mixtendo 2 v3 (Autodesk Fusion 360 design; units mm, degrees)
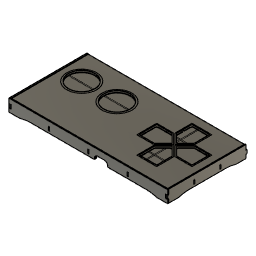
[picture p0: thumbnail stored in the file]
parameter "mt" = 12.7
sketch "Sketch1" plane through (0, 0, 0) normal (0, 0, 1) x axis (1, 0, 0)
  line L1 (12.7, 0) -> (0, 0)
  line L2 (12.7, 914.4) -> (12.7, 0)
  line L3 (0, 914.4) -> (12.7, 914.4)
  line L4 (0, 0) -> (0, 914.4)
  line L5 (1828.8, 0) -> (0, 0)
  line L6 (1828.8, 12.7) -> (1828.8, 0)
  line L7 (0, 12.7) -> (1828.8, 12.7)
  line L8 (0, 0) -> (0, 12.7)
  point P1 (0, 0)
  point P2 (0, 0)
  point P6 (0, 0)
  point P3 (12.7, 0)
  point P5 (0, 914.4)
  point P7 (1828.8, 0)
  point P9 (0, 12.7)
  horizontal L1
  vertical L2
  horizontal L3
  vertical L4
  coincident P1 P2
  horizontal L5
  vertical L6
  horizontal L7
  vertical L8
  coincident P1 P6
  dimension "d2" distance P2 P3 = 12.7 (= "mt")
  dimension "d3" distance P2 P5 = 914.4
  dimension "d4" distance P6 P7 = 1828.8
  dimension "d5" distance P6 P9 = 12.7 (= "mt")
extrude "Extrude1" new body sketch "Sketch1" profile of L1 L2 L3 L4 L5 L7 L8 along normal blind 127 bodies "left vert1"
extrude "Extrude2" new body sketch "Sketch1" profile of L1 L2 L4 L5 L6 L7 L8 along normal blind 139.7 bodies "front horizontal"
rectangular_pattern "R-Pattern1" uSpaceDistance 1816.1 (= "72 in - mt") vSpaceDistance 0 bodies "vert2", "vert3", "vert4", "right vert5"
rectangular_pattern "R-Pattern2" uSpaceDistance 901.7 (= "36 in - mt") vSpaceDistance 0 bodies "horizontal (1)", "horizontal (2)", "rear horiz"
sketch "Sketch2" plane through (0, 0, 127) normal (0, 0, 1) x axis (-1, 0, 0)
  line L1 (0, 0) -> (0, -914.4)
  line L2 (-12.7, 0) -> (0, 0)
  line L3 (-12.7, -914.4) -> (-12.7, 0)
  line L4 (0, -914.4) -> (-12.7, -914.4)
  line L5 (0, 0) -> (0, -12.7)
  line L6 (-1828.8, 0) -> (0, 0)
  line L7 (-1828.8, -12.7) -> (-1828.8, 0)
  line L8 (0, -12.7) -> (-1828.8, -12.7)
  line L9 (0, -20) -> (0, -2.5)
  line L10 (0, -901.7) -> (0, -914.4)
  line L11 (-1828.8, -901.7) -> (0, -901.7)
  line L12 (-1828.8, -914.4) -> (-1828.8, -901.7)
  line L13 (0, -914.4) -> (-1828.8, -914.4)
  line L14 (-1816.1, 0) -> (-1816.1, -914.4)
  line L15 (-1828.8, 0) -> (-1816.1, 0)
  line L16 (-1828.8, -914.4) -> (-1828.8, 0)
  line L17 (-1816.1, -914.4) -> (-1828.8, -914.4)
  line L18 (-1816.1, -901.7) -> (-1803.4, -901.7)
  line L19 (-1816.1, -12.7) -> (-1816.1, -901.7)
  line L20 (-25.4, -914.4) -> (-12.7, -914.4)
  line L21 (-25.4, 0) -> (-25.4, -914.4)
  line L22 (-12.7, 0) -> (-25.4, 0)
  line L23 (-12.7, -914.4) -> (-12.7, 0)
  line L24 (-1803.4, 0) -> (-1816.1, 0)
  line L25 (-1803.4, -914.4) -> (-1803.4, 0)
  line L26 (-1816.1, -914.4) -> (-1803.4, -914.4)
  line L27 (-1816.1, 0) -> (-1816.1, -914.4)
  line L28 (0, -901.7) -> (-1828.8, -901.7)
  line L29 (0, -889) -> (0, -901.7)
  line L30 (-1828.8, -889) -> (0, -889)
  line L31 (-1828.8, -901.7) -> (-1828.8, -889)
  line L32 (-1828.8, -12.7) -> (0, -12.7)
  line L33 (-1828.8, -25.4) -> (-1828.8, -12.7)
  line L34 (0, -25.4) -> (-1828.8, -25.4)
  line L35 (0, -12.7) -> (0, -25.4)
  point P21 (-1803.4, -901.7)
  point P20 (-1816.1, -12.7)
  point P25 (-25.4, 0)
  point P5 (-12.7, -914.4)
  point P23 (-12.7, -914.4)
  point P29 (-1803.4, -914.4)
  point P17 (-1816.1, 0)
  point P27 (-1816.1, 0)
  point P33 (0, -889)
  point P14 (-1828.8, -901.7)
  point P31 (-1828.8, -901.7)
  point P37 (-1828.8, -25.4)
  point P6 (0, -12.7)
  point P35 (0, -12.7)
  horizontal L18
  vertical L19
  coincident L11 P21
  coincident L8 P20
  coincident L14 P20
  horizontal L20
  vertical L21
  horizontal L22
  vertical L23
  coincident L6 P25
  coincident P5 P23
  horizontal L24
  vertical L25
  horizontal L26
  vertical L27
  coincident L13 P29
  coincident P17 P27
  horizontal L28
  vertical L29
  horizontal L30
  vertical L31
  coincident L1 P33
  coincident P14 P31
  horizontal L32
  vertical L33
  horizontal L34
  vertical L35
  coincident L16 P37
  coincident P6 P35
  dimension "d30" distance L21 L23 = 12.7 (= "mt")
  dimension "d31" distance L25 L27 = 12.7 (= "mt")
  dimension "d32" distance L28 L30 = 12.7 (= "mt")
  dimension "d33" distance L32 L34 = 12.7 (= "mt")
extrude "Extrude3" new body sketch "Sketch2" profile of L3 L8 L11 L14 L18 L19 L21 L23 L25 L27 L28 L30 L32 L34 against normal blind 127 bodies "front horiz sup", "rear horiz sup"
extrude "Extrude4" new body sketch "Sketch2" profile of L3 L6 L8 L11 L13 L14 L18 L19 L20 L21 L22 L23 L24 L25 L26 L27 L28 L30 L32 L34 against normal blind 127 bodies "left vert sup", "right vert sup"
sketch "Sketch4" plane through (0, 0, 0) normal (1, 0, 0) x axis (0, 1, 0)
  line L1 (0, 0) -> (914.4, 0)
  line L2 (0, 127) -> (0, 0)
  line L3 (914.4, 127) -> (0, 127)
  line L4 (914.4, 0) -> (914.4, 127)
  line L5 (457.2, 127) -> (457.2, 0)
  line L6 (25.4, 127) -> (0, 127)
  line L7 (25.4, 84.6667) -> (25.4, 127)
  line L8 (0, 84.6667) -> (25.4, 84.6667)
  line L9 (0, 127) -> (0, 84.6667)
  line L10 (0, 63.5) -> (457.2, 63.5)
  line L11 (25.4, 0) -> (0, 0)
  line L12 (25.4, 42.3333) -> (25.4, 0)
  line L13 (0, 0) -> (0, 42.3333)
  line L14 (0, 42.3333) -> (25.4, 42.3333)
  line L15 (889, 127) -> (914.4, 127)
  line L16 (889, 84.6667) -> (889, 127)
  line L17 (914.4, 127) -> (914.4, 84.6667)
  line L18 (914.4, 84.6667) -> (889, 84.6667)
  line L19 (889, 0) -> (914.4, 0)
  line L20 (889, 42.3333) -> (889, 0)
  line L21 (914.4, 0) -> (914.4, 42.3333)
  line L22 (914.4, 42.3333) -> (889, 42.3333)
  point P6 (457.2, 0)
  point P7 (457.2, 127)
  point P4 (0, 127)
  point P8 (0, 127)
  point P12 (457.2, 63.5)
  point P13 (0, 63.5)
  point P14 (0, 0)
  point P9 (25.4, 127)
  point P15 (25.4, 0)
  point P10 (25.4, 84.6667)
  point P16 (25.4, 42.3333)
  point P11 (0, 84.6667)
  point P17 (0, 42.3333)
  point P18 (914.4, 127)
  point P19 (889, 127)
  point P20 (889, 84.6667)
  point P21 (914.4, 84.6667)
  point P22 (914.4, 0)
  point P23 (889, 0)
  point P24 (889, 42.3333)
  point P25 (914.4, 42.3333)
  midpoint L1 P6
  midpoint L3 P7
  horizontal L6
  vertical L7
  horizontal L8
  vertical L9
  coincident P4 P8
  midpoint L5 P12
  midpoint L2 P13
  symmetric P8 L10 P14
  symmetric P9 L10 P15
  symmetric P10 L10 P16
  symmetric P11 L10 P17
  symmetric L5 P8 P18
  symmetric L5 P9 P19
  symmetric L5 P10 P20
  symmetric L5 P11 P21
  symmetric L5 P14 P22
  symmetric L5 P15 P23
  symmetric L5 P16 P24
  symmetric L5 P17 P25
  dimension "d26" distance P8 P9 = 25.4 (= "mt * 2")
  dimension "d27" distance P8 P11 = 42.3333 (= "( 5 / 3 ) * 1 in")
extrude "Extrude6" cut sketch "Sketch4" profile of L1 L2 L3 L4 L6 L7 L8 L9 L11 L12 L13 L14 L15 L16 L17 L18 L19 L20 L21 L22 to an object
combine "Combine1"
combine "Combine2"
combine "Combine3"
combine "Combine4"
sketch "Sketch5" plane through (0, 300.5667, 0) normal (0, -1, 0) x axis (1, 0, 0)
  line L1 (1828.8, 0) -> (0, 0)
  line L2 (1828.8, 139.7) -> (1828.8, 0)
  line L3 (0, 139.7) -> (1828.8, 139.7)
  line L4 (0, 0) -> (0, 139.7)
  line L5 (1374.775, 84.6667) -> (1362.075, 84.6667)
  line L6 (1374.775, 42.3333) -> (1374.775, 84.6667)
  line L7 (1362.075, 42.3333) -> (1374.775, 42.3333)
  line L8 (1362.075, 84.6667) -> (1362.075, 42.3333)
  line L9 (1803.4, 42.3333) -> (1828.8, 42.3333)
  line L10 (1803.4, 84.6667) -> (1803.4, 42.3333)
  line L11 (1828.8, 84.6667) -> (1803.4, 84.6667)
  line L12 (1828.8, 139.7) -> (1828.8, 84.6667)
  line L13 (0, 139.7) -> (1828.8, 139.7)
  line L14 (0, 84.6667) -> (0, 139.7)
  line L15 (25.4, 84.6667) -> (0, 84.6667)
  line L16 (25.4, 42.3333) -> (25.4, 84.6667)
  line L17 (0, 42.3333) -> (25.4, 42.3333)
  line L18 (0, 0) -> (0, 42.3333)
  line L19 (1828.8, 0) -> (0, 0)
  line L20 (1828.8, 42.3333) -> (1828.8, 0)
  line L21 (466.725, 84.6667) -> (454.025, 84.6667)
  line L22 (466.725, 42.3333) -> (466.725, 84.6667)
  line L23 (454.025, 42.3333) -> (466.725, 42.3333)
  line L24 (454.025, 84.6667) -> (454.025, 42.3333)
  line L25 (920.75, 84.6667) -> (908.05, 84.6667)
  line L26 (920.75, 42.3333) -> (920.75, 84.6667)
  line L27 (908.05, 42.3333) -> (920.75, 42.3333)
  line L28 (908.05, 84.6667) -> (908.05, 42.3333)
  line L29 (25.4, 84.6667) -> (0, 84.6667)
  line L30 (25.4, 139.7) -> (25.4, 84.6667)
  line L31 (0, 139.7) -> (25.4, 139.7)
  line L32 (0, 84.6667) -> (0, 139.7)
  line L33 (0, 42.3333) -> (25.4, 42.3333)
  line L34 (0, 0) -> (0, 42.3333)
  line L35 (25.4, 0) -> (0, 0)
  line L36 (25.4, 42.3333) -> (25.4, 0)
  line L37 (1828.8, 84.6667) -> (1803.4, 84.6667)
  line L38 (1828.8, 139.7) -> (1828.8, 84.6667)
  line L39 (1803.4, 139.7) -> (1828.8, 139.7)
  line L40 (1803.4, 84.6667) -> (1803.4, 139.7)
  line L41 (1828.8, 42.3333) -> (1803.4, 42.3333)
  line L42 (1828.8, 0) -> (1828.8, 42.3333)
  line L43 (1803.4, 0) -> (1828.8, 0)
  line L44 (1803.4, 42.3333) -> (1803.4, 0)
  point P32 (25.4, 139.7)
  point P16 (0, 84.6667)
  point P30 (0, 84.6667)
  point P2 (0, 0)
  point P36 (0, 0)
  point P18 (25.4, 42.3333)
  point P34 (25.4, 42.3333)
  point P14 (1828.8, 139.7)
  point P40 (1828.8, 139.7)
  point P12 (1803.4, 84.6667)
  point P38 (1803.4, 84.6667)
  point P21 (1828.8, 0)
  point P44 (1828.8, 0)
  point P11 (1803.4, 42.3333)
  point P42 (1803.4, 42.3333)
  horizontal L29
  vertical L30
  horizontal L31
  vertical L32
  coincident L3 P32
  coincident P16 P30
  horizontal L33
  vertical L34
  horizontal L35
  vertical L36
  coincident P2 P36
  coincident P18 P34
  horizontal L37
  vertical L38
  horizontal L39
  vertical L40
  coincident P14 P40
  coincident P12 P38
  horizontal L41
  vertical L42
  horizontal L43
  vertical L44
  coincident P21 P44
  coincident P11 P42
extrude "Extrude7" cut sketch "Sketch5" profile of L1 L2 L3 L4 L9 L11 L12 L13 L14 L15 L17 L18 L19 L20 L29 L30 L31 L32 L33 L34 L35 L36 L37 L38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 to an object
combine "Combine5"
combine "Combine6"
combine "Combine7"
combine "Combine8"
sketch "Sketch6" plane through (1828.8, 0, 0) normal (1, 0, 0) x axis (0, 1, 0)
  line L1 (313.2667, 84.6667) -> (300.5667, 84.6667)
  line L2 (313.2667, 42.3333) -> (313.2667, 84.6667)
  line L3 (300.5667, 42.3333) -> (313.2667, 42.3333)
  line L4 (300.5667, 84.6667) -> (300.5667, 42.3333)
  line L5 (613.8333, 84.6667) -> (601.1333, 84.6667)
  line L6 (613.8333, 42.3333) -> (613.8333, 84.6667)
  line L7 (601.1333, 42.3333) -> (613.8333, 42.3333)
  line L8 (601.1333, 84.6667) -> (601.1333, 42.3333)
  line L9 (25.4, 0) -> (25.4, 42.3333)
  line L10 (889, 0) -> (25.4, 0)
  line L11 (889, 42.3333) -> (889, 0)
  line L12 (914.4, 42.3333) -> (889, 42.3333)
  line L13 (914.4, 84.6667) -> (914.4, 42.3333)
  line L14 (889, 84.6667) -> (914.4, 84.6667)
  line L15 (889, 127) -> (889, 84.6667)
  line L16 (25.4, 127) -> (889, 127)
  line L17 (25.4, 84.6667) -> (25.4, 127)
  line L18 (0, 84.6667) -> (25.4, 84.6667)
  line L19 (0, 42.3333) -> (0, 84.6667)
  line L20 (25.4, 42.3333) -> (0, 42.3333)
  line L21 (313.2667, 127) -> (300.5667, 127)
  line L22 (313.2667, 63.5) -> (313.2667, 127)
  line L23 (300.5667, 63.5) -> (313.2667, 63.5)
  line L24 (300.5667, 127) -> (300.5667, 63.5)
  line L25 (601.1333, 127) -> (613.8333, 127)
  line L26 (601.1333, 63.5) -> (601.1333, 127)
  line L27 (613.8333, 63.5) -> (601.1333, 63.5)
  line L28 (613.8333, 127) -> (613.8333, 63.5)
  point P24 (313.2667, 63.5)
  point P22 (300.5667, 127)
  point P26 (613.8333, 127)
  horizontal L21
  vertical L22
  horizontal L23
  vertical L24
  coincident L2 P24
  coincident L16 P22
  horizontal L25
  vertical L26
  horizontal L27
  vertical L28
  coincident L16 P26
  dimension "d40" distance L21 L23 = 63.5
  dimension "d41" distance L22 L24 = 12.7 (= "mt")
  dimension "d42" distance L26 L28 = 12.7 (= "mt")
  dimension "d43" distance L25 L27 = 63.5
extrude "Extrude8" cut sketch "Sketch6" profile of L1 L2 L4 L5 L6 L8 L16 L21 L22 L23 L24 L25 L26 L27 L28 to an object
combine "Combine9"
combine "Combine10"
sketch "Sketch9" plane through (0, 0, 127) normal (0, 0, 1) x axis (-1, 0, 0)
  line L1 (0, -889) -> (-12.7, -889)
  line L2 (0, -25.4) -> (0, -889)
  line L3 (-12.7, -25.4) -> (0, -25.4)
  line L4 (-12.7, -889) -> (-12.7, -25.4)
  line L5 (0, 0) -> (0, -12.7)
  line L6 (-1828.8, 0) -> (0, 0)
  line L7 (-1828.8, -12.7) -> (-1828.8, 0)
  line L8 (0, -12.7) -> (-1828.8, -12.7)
  line L9 (-12.7, -25.4) -> (-12.7, 0)
  line L10 (0, -25.4) -> (-12.7, -25.4)
  line L11 (0, 0) -> (0, -25.4)
  line L12 (-12.7, 0) -> (0, 0)
  line L13 (0, -901.7) -> (0, -914.4)
  line L14 (-1828.8, -901.7) -> (0, -901.7)
  line L15 (-1828.8, -914.4) -> (-1828.8, -901.7)
  line L16 (0, -914.4) -> (-1828.8, -914.4)
  line L17 (-12.7, -914.4) -> (-12.7, -889)
  line L18 (0, -914.4) -> (-12.7, -914.4)
  line L19 (0, -889) -> (0, -914.4)
  line L20 (-12.7, -889) -> (0, -889)
  line L21 (-1816.1, -889) -> (-1816.1, -914.4)
  line L22 (-1828.8, -889) -> (-1816.1, -889)
  line L23 (-1828.8, -914.4) -> (-1828.8, -889)
  line L24 (-1816.1, -914.4) -> (-1828.8, -914.4)
  line L25 (-1816.1, -889) -> (-1828.8, -889)
  line L26 (-1816.1, -25.4) -> (-1816.1, -889)
  line L27 (-1828.8, -25.4) -> (-1816.1, -25.4)
  line L28 (-1828.8, -889) -> (-1828.8, -25.4)
  line L29 (-1816.1, 0) -> (-1816.1, -25.4)
  line L30 (-1828.8, 0) -> (-1816.1, 0)
  line L31 (-1828.8, -25.4) -> (-1828.8, 0)
  line L32 (-1816.1, -25.4) -> (-1828.8, -25.4)
  line L33 (-1816.1, -12.7) -> (-1828.8, -12.7)
  line L34 (-1816.1, -25.4) -> (-1816.1, -12.7)
  line L35 (-1828.8, -25.4) -> (-1816.1, -25.4)
  line L36 (-1828.8, -12.7) -> (-1828.8, -25.4)
  line L37 (-1816.1, -889) -> (-1828.8, -889)
  line L38 (-1816.1, -901.7) -> (-1816.1, -889)
  line L39 (-1828.8, -901.7) -> (-1816.1, -901.7)
  line L40 (-1828.8, -889) -> (-1828.8, -901.7)
  line L41 (-12.7, -889) -> (0, -889)
  line L42 (-12.7, -901.7) -> (-12.7, -889)
  line L43 (0, -901.7) -> (-12.7, -901.7)
  line L44 (0, -889) -> (0, -901.7)
  line L45 (-12.7, -12.7) -> (0, -12.7)
  line L46 (-12.7, -25.4) -> (-12.7, -12.7)
  line L47 (0, -25.4) -> (-12.7, -25.4)
  line L48 (0, -12.7) -> (0, -25.4)
  point P28 (-1816.1, -25.4)
  point P36 (-1816.1, -25.4)
  point P9 (-1828.8, -12.7)
  point P34 (-1828.8, -12.7)
  point P40 (-1816.1, -901.7)
  point P26 (-1828.8, -889)
  point P38 (-1828.8, -889)
  point P44 (-12.7, -901.7)
  point P21 (0, -889)
  point P42 (0, -889)
  point P5 (-12.7, -25.4)
  point P48 (-12.7, -25.4)
  point P6 (0, -12.7)
  point P46 (0, -12.7)
  horizontal L33
  vertical L34
  horizontal L35
  vertical L36
  coincident P28 P36
  coincident P9 P34
  horizontal L37
  vertical L38
  horizontal L39
  vertical L40
  midpoint L21 P40
  coincident P26 P38
  horizontal L41
  vertical L42
  horizontal L43
  vertical L44
  midpoint L17 P44
  coincident P21 P42
  horizontal L45
  vertical L46
  horizontal L47
  vertical L48
  coincident P5 P48
  coincident P6 P46
extrude "Extrude10" add sketch "Sketch9" profile of L1 L3 L8 L9 L10 L11 L14 L17 L19 L20 L21 L22 L23 L25 L27 L29 L31 L32 L33 L34 L35 L36 L37 L38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 to an object
extrude "Extrude11" cut of existing geometry blind -25.4
sketch "Sketch11" plane through (0, 0, 101.6) normal (0, 0, 1) x axis (-1, 0, 0)
  line L1 (-1816.1, -889) -> (-12.7, -889)
  line L2 (-1816.1, -901.7) -> (-1816.1, -889)
  line L3 (-12.7, -901.7) -> (-1816.1, -901.7)
  line L4 (-12.7, -889) -> (-12.7, -901.7)
  line L5 (-1803.4, -889) -> (-1803.4, -914.4)
  line L6 (-1803.4, -889) -> (-1803.4, -25.4)
  line L7 (-1803.4, 0) -> (-1803.4, -25.4)
  line L8 (-1816.1, -25.4) -> (-1816.1, 0)
  line L9 (-1816.1, -25.4) -> (-1816.1, -889)
  line L10 (-1816.1, -914.4) -> (-1816.1, -889)
  line L11 (-1816.1, 0) -> (-1803.4, 0)
  line L12 (-1803.4, -914.4) -> (-1816.1, -914.4)
  line L13 (-1816.1, -901.7) -> (-12.7, -901.7)
  line L14 (-12.7, -889) -> (-1816.1, -889)
  line L15 (-1816.1, -889) -> (-1816.1, -901.7)
  line L16 (-12.7, -901.7) -> (-12.7, -889)
  line L17 (-25.4, -25.4) -> (-25.4, 0)
  line L18 (-25.4, -25.4) -> (-25.4, -889)
  line L19 (-25.4, -914.4) -> (-25.4, -889)
  line L20 (-25.4, 0) -> (-12.7, 0)
  line L21 (-12.7, 0) -> (-12.7, -25.4)
  line L22 (-12.7, -889) -> (-12.7, -914.4)
  line L23 (-12.7, -914.4) -> (-25.4, -914.4)
  line L24 (-12.7, -889) -> (-12.7, -25.4)
  line L25 (-1816.1, -25.4) -> (-12.7, -25.4)
  line L26 (-12.7, -25.4) -> (-12.7, -12.7)
  line L27 (-12.7, -12.7) -> (-1816.1, -12.7)
  line L28 (-1816.1, -12.7) -> (-1816.1, -25.4)
  line L29 (-12.7, -901.7) -> (-1816.1, -901.7)
  line L30 (-12.7, -12.7) -> (-12.7, -901.7)
  line L31 (-1816.1, -12.7) -> (-12.7, -12.7)
  line L32 (-1816.1, -901.7) -> (-1816.1, -12.7)
  point P28 (-12.7, -12.7)
  point P32 (-12.7, -12.7)
  point P15 (-1816.1, -901.7)
  point P30 (-1816.1, -901.7)
  horizontal L29
  vertical L30
  horizontal L31
  vertical L32
  coincident P28 P32
  coincident P15 P30
extrude "Extrude12" new body sketch "Sketch11" profile of L1 L2 L3 L4 L5 L6 L7 L8 L9 L10 L13 L14 L15 L16 L17 L18 L19 L21 L22 L24 L25 L26 L27 L28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 along normal blind 12.7 (= "mt") bodies "base"
sketch "Sketch12" plane through (0, 0, 114.3) normal (0, 0, 1) x axis (-1, 0, 0)
  line L1 (-1816.1, -901.7) -> (-1816.1, -12.7)
  line L2 (-12.7, -901.7) -> (-1816.1, -901.7)
  line L3 (-12.7, -12.7) -> (-12.7, -901.7)
  line L4 (-1816.1, -12.7) -> (-12.7, -12.7)
  line L5 (-1816.1, -12.7) -> (-12.7, -12.7)
  line L6 (-12.7, -12.7) -> (-12.7, -901.7)
  line L7 (-12.7, -901.7) -> (-1816.1, -901.7)
  line L8 (-1816.1, -901.7) -> (-1816.1, -12.7)
  line L9 (-12.7, -12.7) -> (-1816.1, -12.7)
  line L10 (-12.7, -901.7) -> (-12.7, -12.7)
  line L11 (-1816.1, -901.7) -> (-12.7, -901.7)
  line L12 (-1816.1, -12.7) -> (-1816.1, -901.7)
  point P8 (-12.7, -901.7)
  point P12 (-12.7, -901.7)
  point P7 (-1816.1, -12.7)
  point P10 (-1816.1, -12.7)
  horizontal L9
  vertical L10
  horizontal L11
  vertical L12
  coincident P8 P12
  coincident P7 P10
extrude "Extrude13" new body sketch "Sketch12" along normal blind 12.7 (= "mt") bodies "flex"
sketch "Sketch13" plane through (0, 0, 114.3) normal (0, 0, 1) x axis (-1, 0, 0)
  line L1 (-1816.1, -901.7) -> (-1816.1, -12.7)
  line L2 (-12.7, -901.7) -> (-1816.1, -901.7)
  line L3 (-12.7, -12.7) -> (-12.7, -901.7)
  line L4 (-1816.1, -12.7) -> (-12.7, -12.7)
  line L5 (-12.7, -457.2) -> (-1816.1, -457.2)
  line L6 (-914.4, -901.7) -> (-914.4, -12.7)
  line L7 (-1308.1, -622.3) -> (-1511.3, -622.3)
  line L8 (-1308.1, -800.1) -> (-1308.1, -622.3)
  line L9 (-1511.3, -800.1) -> (-1308.1, -800.1)
  line L10 (-1511.3, -622.3) -> (-1511.3, -800.1)
  line L11 (-1409.7, -745.3943) -> (-1409.7, -800.1)
  line L12 (-1409.7, -520.7) -> (-1409.7, -745.3943)
  line L13 (-1511.3, -622.3) -> (-1409.7, -520.7)
  line L14 (-1308.1, -622.3) -> (-1409.7, -520.7)
  line L15 (-1105.1994, -596.6041) -> (-1105.1994, -393.4041)
  line L16 (-1282.9994, -596.6041) -> (-1105.1994, -596.6041)
  line L17 (-1105.1994, -393.4041) -> (-1282.9994, -393.4041)
  line L18 (-1282.9994, -393.4041) -> (-1384.5994, -495.0041)
  line L19 (-1282.9994, -596.6041) -> (-1384.5994, -495.0041)
  line L20 (-1308.6953, -190.5035) -> (-1511.8953, -190.5035)
  line L21 (-1308.6953, -368.3035) -> (-1308.6953, -190.5035)
  line L22 (-1511.8953, -190.5035) -> (-1511.8953, -368.3035)
  line L23 (-1511.8953, -368.3035) -> (-1410.2953, -469.9035)
  line L24 (-1308.6953, -368.3035) -> (-1410.2953, -469.9035)
  line L25 (-1714.7959, -393.9994) -> (-1714.7959, -597.1994)
  line L26 (-1536.9959, -393.9994) -> (-1714.7959, -393.9994)
  line L27 (-1714.7959, -597.1994) -> (-1536.9959, -597.1994)
  line L28 (-1536.9959, -597.1994) -> (-1435.3959, -495.5994)
  line L29 (-1536.9959, -393.9994) -> (-1435.3959, -495.5994)
  line L30 (-12.7, -596.9) -> (-914.4, -596.9)
  line L31 (-838.2, -63.5) -> (-990.6, -63.5)
  line L32 (-838.2, -139.7) -> (-838.2, -63.5)
  line L33 (-990.6, -139.7) -> (-838.2, -139.7)
  line L34 (-990.6, -63.5) -> (-990.6, -139.7)
  line L35 (-838.2, -139.7) -> (-990.6, -63.5)
  line L36 (-990.6, -139.7) -> (-838.2, -63.5)
  line L37 (-1625.8959, -101.6) -> (-1625.8959, -393.9994)
  line L38 (-990.6, -101.6) -> (-1625.8959, -101.6)
  line L39 (-1644.9459, -82.55) -> (-1644.9459, -393.9994)
  line L40 (-990.6, -82.55) -> (-1644.9459, -82.55)
  line L41 (-1410.2953, -101.6) -> (-1410.2953, -190.5035)
  line L42 (-1194.0994, -101.6) -> (-1194.0994, -393.4041)
  line L43 (-1429.3453, -101.6) -> (-1429.3453, -190.5035)
  line L44 (-1175.0494, -101.6) -> (-1175.0494, -393.4041)
  line L45 (-1041.4, -711.2) -> (-1308.1, -711.2)
  line L46 (-1041.4, -101.6) -> (-1041.4, -711.2)
  line L47 (-1060.45, -692.15) -> (-1308.1, -692.15)
  line L48 (-1060.45, -101.6) -> (-1060.45, -692.15)
  line L49 (-445.2488, -101.6) -> (-838.2, -101.6)
  line L50 (-445.2488, -101.6) -> (-267.2164, -446.7198)
  line L51 (-456.8571, -120.65) -> (-838.2, -120.65)
  line L52 (-456.8571, -120.65) -> (-286.2927, -451.2929)
  line L53 (-596.9, -495.3) -> (-596.9, -740.5841)
  line L54 (-596.9, -120.65) -> (-596.9, -495.3)
  line L55 (-615.95, -495.3) -> (-615.95, -447.844)
  line L56 (-615.95, -120.65) -> (-615.95, -495.3)
  circle C1 centre (-647.7, -596.9) radius 152.4
  circle C2 centre (-241.3, -596.9) radius 152.4
  circle C3 centre (-1409.9977, -495.3017) radius 14.1473
  point P6 (-1816.1, -457.2)
  point P7 (-12.7, -457.2)
  point P8 (-914.4, -12.7)
  point P9 (-914.4, -901.7)
  point P16 (-1409.7, -800.1)
  point P35 (-914.4, -596.9)
  point P36 (-12.7, -596.9)
  point P10 (-647.7, -596.9)
  point P11 (-241.3, -596.9)
  point P41 (-914.4, -101.6)
  point P42 (-1625.8959, -393.9994)
  point P44 (-990.6, -101.6)
  point P48 (-1410.2953, -190.5035)
  point P49 (-1410.2953, -101.6)
  point P50 (-1194.0994, -393.4041)
  point P56 (-1308.1, -711.2)
  point P58 (-1041.4, -101.6)
  point P62 (-838.2, -101.6)
  point P63 (-267.2164, -446.7198)
  point P67 (-286.2927, -451.2929)
  point P68 (-596.9, -740.5841)
  point P70 (-596.9, -120.65)
  point P73 (-615.95, -447.844)
  point P18 (-1409.7, -520.7)
  point P19 (-1409.9977, -495.3017)
  point P39 (-838.2, -139.7)
  point P40 (-990.6, -139.7)
  point P38 (-838.2, -63.5)
  midpoint L1 P6
  midpoint L3 P7
  midpoint L4 P8
  midpoint L2 P9
  horizontal L7
  vertical L8
  horizontal L9
  vertical L10
  midpoint L9 P16
  perpendicular L9 L11
  perpendicular L9 L12
  coincident L6 P35
  coincident L3 P36
  perpendicular L3 L30
  coincident P10 L30
  coincident P11 L30
  horizontal L31
  perpendicular L31 L32
  parallel L31 L33
  parallel L32 L34
  coincident L35 P41
  coincident L36 P41
  coincident L6 P41
  midpoint L26 P42
  perpendicular L26 L37
  midpoint L34 P44
  perpendicular L37 L38
  midpoint L20 P48
  coincident L38 P49
  perpendicular L38 L41
  midpoint L17 P50
  perpendicular L17 L42
  midpoint L8 P56
  perpendicular L8 L45
  coincident L38 P58
  perpendicular L38 L46
  midpoint L32 P62
  perpendicular L32 L49
  coincident C2 P63
  coincident C2 P67
  coincident C1 P68
  perpendicular L5 L53
  coincident L51 P70
  perpendicular L51 L54
  coincident C1 P73
  dimension "d56" diameter C1 = 304.8
  dimension "d57" diameter C2 = 304.8
  dimension "d58" distance L8 L10 = 203.2
  dimension "d59" distance L9 P18 = 279.4
  dimension "d60" distance P18 P19 = 25.4
  dimension "d61" angle L7 L13 = 45
  dimension "d64" distance L1 L10 = 304.8
  dimension "d65" distance L2 L9 = 101.6
  dimension "d66" distance L2 L30 = 304.8
  dimension "d67" distance L3 P11 = 228.6
  dimension "d68" distance P10 P11 = 406.4
  dimension "d69" distance P39 P40 = 152.4
  dimension "d70" distance P38 P39 = 76.2
  dimension "d71" distance L4 L31 = 50.8
  dimension "d72" = -19.05
  dimension "d73" = -19.05
  dimension "d74" = 19.05
  dimension "d75" = -19.05
  dimension "d63" C-Pattern1-Angle = 360
extrude "Extrude14" cut sketch "Sketch13" profile of L31 L32 L33 L34 to an object
extrude "Extrude15" cut sketch "Sketch13" profile of C1 C2 L7 L8 L9 L10 L11 L12 L13 L14 L15 L16 L17 L18 L19 L20 L21 L22 L23 L24 L25 L26 L27 L28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 against normal blind 6.35
fillet "Fillet1" radius 19.05
sketch "Sketch14" plane through (0, 0, 127) normal (0, 0, 1) x axis (-1, 0, 0)
  line L1 (-12.7, -901.7) -> (-1816.1, -901.7)
  line L2 (-12.7, -12.7) -> (-12.7, -901.7)
  line L3 (-1816.1, -12.7) -> (-12.7, -12.7)
  line L4 (-1816.1, -901.7) -> (-1816.1, -12.7)
  line L5 (-1511.3, -800.1) -> (-1308.1, -800.1)
  line L6 (-1511.3, -622.3) -> (-1511.3, -800.1)
  line L7 (-1308.1, -800.1) -> (-1308.1, -622.3)
  line L8 (-1308.1, -622.3) -> (-1409.7, -520.7)
  line L9 (-1511.3, -622.3) -> (-1409.7, -520.7)
  line L10 (-1282.9994, -596.6041) -> (-1384.5994, -495.0041)
  line L11 (-1282.9994, -393.4041) -> (-1384.5994, -495.0041)
  line L12 (-1105.1994, -393.4041) -> (-1282.9994, -393.4041)
  line L13 (-1105.1994, -596.6041) -> (-1105.1994, -393.4041)
  line L14 (-1282.9994, -596.6041) -> (-1105.1994, -596.6041)
  line L15 (-1308.6953, -190.5035) -> (-1511.8953, -190.5035)
  line L16 (-1511.8953, -190.5035) -> (-1511.8953, -368.3035)
  line L17 (-1511.8953, -368.3035) -> (-1410.2953, -469.9035)
  line L18 (-1308.6953, -368.3035) -> (-1410.2953, -469.9035)
  line L19 (-1308.6953, -368.3035) -> (-1308.6953, -190.5035)
  line L20 (-1536.9959, -393.9994) -> (-1714.7959, -393.9994)
  line L21 (-1714.7959, -393.9994) -> (-1714.7959, -597.1994)
  line L22 (-1714.7959, -597.1994) -> (-1536.9959, -597.1994)
  line L23 (-1536.9959, -597.1994) -> (-1435.3959, -495.5994)
  line L24 (-1536.9959, -393.9994) -> (-1435.3959, -495.5994)
  circle C1 centre (-241.3, -596.9) radius 152.4
  circle C2 centre (-647.7, -596.9) radius 152.4
extrude "Extrude16" new body sketch "Sketch14" along normal blind 6.35 bodies "faceplate"
sketch "Sketch15" plane through (0, 0, 127) normal (0, 0, -1) x axis (1, 0, 0)
  line L1 (1308.6953, -368.3035) -> (1410.2953, -469.9035)
  line L2 (1308.6953, -190.5035) -> (1308.6953, -368.3035)
  line L3 (1511.8953, -190.5035) -> (1308.6953, -190.5035)
  line L4 (1511.8953, -368.3035) -> (1511.8953, -190.5035)
  line L5 (1410.2953, -469.9035) -> (1511.8953, -368.3035)
  line L6 (1435.3959, -495.5994) -> (1536.9959, -597.1994)
  line L7 (1536.9959, -393.9994) -> (1435.3959, -495.5994)
  line L8 (1714.7959, -393.9994) -> (1536.9959, -393.9994)
  line L9 (1714.7959, -597.1994) -> (1714.7959, -393.9994)
  line L10 (1536.9959, -597.1994) -> (1714.7959, -597.1994)
  line L11 (1409.7, -520.7) -> (1308.1, -622.3)
  line L12 (1511.3, -622.3) -> (1409.7, -520.7)
  line L13 (1511.3, -800.1) -> (1511.3, -622.3)
  line L14 (1308.1, -800.1) -> (1511.3, -800.1)
  line L15 (1308.1, -622.3) -> (1308.1, -800.1)
  line L16 (1282.9994, -596.6041) -> (1384.5994, -495.0041)
  line L17 (1105.1994, -596.6041) -> (1282.9994, -596.6041)
  line L18 (1105.1994, -393.4041) -> (1105.1994, -596.6041)
  line L19 (1282.9994, -393.4041) -> (1105.1994, -393.4041)
  line L20 (1384.5994, -495.0041) -> (1282.9994, -393.4041)
  line L21 (1816.1, -12.7) -> (1816.1, -901.7)
  line L22 (12.7, -12.7) -> (1816.1, -12.7)
  line L23 (12.7, -901.7) -> (12.7, -12.7)
  line L24 (1816.1, -901.7) -> (12.7, -901.7)
  line L25 (1524.5953, -373.564) -> (1524.5953, -177.8035)
  line L26 (1410.2953, -487.864) -> (1524.5953, -373.564)
  line L27 (1295.9953, -373.564) -> (1410.2953, -487.864)
  line L28 (1295.9953, -177.8035) -> (1295.9953, -373.564)
  line L29 (1524.5953, -177.8035) -> (1295.9953, -177.8035)
  line L30 (1524, -617.0395) -> (1409.7, -502.7395)
  line L31 (1524, -812.8) -> (1524, -617.0395)
  line L32 (1295.4, -812.8) -> (1524, -812.8)
  line L33 (1295.4, -617.0395) -> (1295.4, -812.8)
  line L34 (1409.7, -502.7395) -> (1295.4, -617.0395)
  line L35 (1727.4959, -609.8994) -> (1727.4959, -381.2994)
  line L36 (1531.7354, -609.8994) -> (1727.4959, -609.8994)
  line L37 (1417.4354, -495.5994) -> (1531.7354, -609.8994)
  line L38 (1531.7354, -381.2994) -> (1417.4354, -495.5994)
  line L39 (1727.4959, -381.2994) -> (1531.7354, -381.2994)
  line L40 (1288.2599, -380.7041) -> (1092.4994, -380.7041)
  line L41 (1402.5599, -495.0041) -> (1288.2599, -380.7041)
  line L42 (1288.2599, -609.3041) -> (1402.5599, -495.0041)
  line L43 (1092.4994, -609.3041) -> (1288.2599, -609.3041)
  line L44 (1092.4994, -380.7041) -> (1092.4994, -609.3041)
  circle C1 centre (241.3, -596.9) radius 152.4
  circle C2 centre (647.7, -596.9) radius 152.4
  circle C3 centre (647.7, -596.9) radius 171.45
  circle C4 centre (241.3, -596.9) radius 171.45
  dimension "d86" = -12.7
  dimension "d87" = 19.05
  dimension "d88" = 19.05
extrude "Extrude17" cut sketch "Sketch15" profile of L1 L2 L3 L4 L5 L6 L7 L8 L9 L10 L11 L12 L13 L14 L15 C1 C2 L16 L17 L18 L19 L20 L30 L40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 against normal blind 2.54
offset_faces "OffsetFaces1" distance 12.7
offset_faces "OffsetFaces2" distance 12.7
sketch "Sketch16" plane through (0, 0, 0) normal (0, -1, 0) x axis (1, 0, 0)
  line L1 (1374.775, 84.6667) -> (1362.075, 84.6667)
  line L2 (1374.775, 42.3333) -> (1374.775, 84.6667)
  line L3 (1362.075, 42.3333) -> (1374.775, 42.3333)
  line L4 (1362.075, 84.6667) -> (1362.075, 42.3333)
  line L5 (1803.4, 42.3333) -> (1828.8, 42.3333)
  line L6 (1803.4, 84.6667) -> (1803.4, 42.3333)
  line L7 (1828.8, 84.6667) -> (1803.4, 84.6667)
  line L8 (1828.8, 139.7) -> (1828.8, 84.6667)
  line L9 (0, 139.7) -> (1828.8, 139.7)
  line L10 (0, 84.6667) -> (0, 139.7)
  line L11 (25.4, 84.6667) -> (0, 84.6667)
  line L12 (25.4, 42.3333) -> (25.4, 84.6667)
  line L13 (0, 42.3333) -> (25.4, 42.3333)
  line L14 (0, 0) -> (0, 42.3333)
  line L15 (1828.8, 0) -> (0, 0)
  line L16 (1828.8, 42.3333) -> (1828.8, 0)
  line L17 (466.725, 84.6667) -> (454.025, 84.6667)
  line L18 (466.725, 42.3333) -> (466.725, 84.6667)
  line L19 (454.025, 42.3333) -> (466.725, 42.3333)
  line L20 (454.025, 84.6667) -> (454.025, 42.3333)
  line L21 (920.75, 84.6667) -> (908.05, 84.6667)
  line L22 (920.75, 42.3333) -> (920.75, 84.6667)
  line L23 (908.05, 42.3333) -> (920.75, 42.3333)
  line L24 (908.05, 84.6667) -> (908.05, 42.3333)
  line L25 (1136.65, 69.85) -> (984.25, 69.85)
  line L26 (1136.65, 19.05) -> (1136.65, 69.85)
  line L27 (984.25, 19.05) -> (1136.65, 19.05)
  line L28 (984.25, 69.85) -> (984.25, 19.05)
  horizontal L25
  vertical L26
  horizontal L27
  vertical L28
  dimension "d93" distance L25 L27 = 50.8
  dimension "d94" distance L26 L28 = 152.4
  dimension "d95" distance L15 L27 = 19.05
  dimension "d96" distance L22 L28 = 63.5
extrude "Extrude18" cut sketch "Sketch16" profile of L25 L26 L27 L28 to an object
sketch "Sketch17" plane through (0, 914.4, 0) normal (0, 1, 0) x axis (-1, 0, 0)
  line L1 (-1374.775, 42.3333) -> (-1362.075, 42.3333)
  line L2 (-1374.775, 84.6667) -> (-1374.775, 42.3333)
  line L3 (-1362.075, 84.6667) -> (-1374.775, 84.6667)
  line L4 (-1362.075, 42.3333) -> (-1362.075, 84.6667)
  line L5 (-1803.4, 84.6667) -> (-1828.8, 84.6667)
  line L6 (-1803.4, 42.3333) -> (-1803.4, 84.6667)
  line L7 (-1828.8, 42.3333) -> (-1803.4, 42.3333)
  line L8 (-1828.8, 0) -> (-1828.8, 42.3333)
  line L9 (0, 0) -> (-1828.8, 0)
  line L10 (0, 42.3333) -> (0, 0)
  line L11 (-25.4, 42.3333) -> (0, 42.3333)
  line L12 (-25.4, 84.6667) -> (-25.4, 42.3333)
  line L13 (0, 84.6667) -> (-25.4, 84.6667)
  line L14 (0, 139.7) -> (0, 84.6667)
  line L15 (-1828.8, 139.7) -> (0, 139.7)
  line L16 (-1828.8, 84.6667) -> (-1828.8, 139.7)
  line L17 (-466.725, 42.3333) -> (-454.025, 42.3333)
  line L18 (-466.725, 84.6667) -> (-466.725, 42.3333)
  line L19 (-454.025, 84.6667) -> (-466.725, 84.6667)
  line L20 (-454.025, 42.3333) -> (-454.025, 84.6667)
  line L21 (-920.75, 42.3333) -> (-908.05, 42.3333)
  line L22 (-920.75, 84.6667) -> (-920.75, 42.3333)
  line L23 (-908.05, 84.6667) -> (-920.75, 84.6667)
  line L24 (-908.05, 42.3333) -> (-908.05, 84.6667)
  line L25 (-127, 0) -> (-1701.8, 0)
  line L26 (-127, 19.05) -> (-127, 0)
  line L27 (-1701.8, 19.05) -> (-127, 19.05)
  line L28 (-1701.8, 0) -> (-1701.8, 19.05)
  point P26 (-1701.8, 0)
  horizontal L25
  vertical L26
  horizontal L27
  vertical L28
  coincident L9 P26
  dimension "d99" distance L26 L28 = 1574.8
  dimension "d100" distance L8 L28 = 127
  dimension "d101" distance L25 L27 = 19.05
sketch "Sketch18" plane through (1828.8, 0, 0) normal (1, 0, 0) x axis (0, 1, 0)
  line L1 (613.8333, 84.6667) -> (601.1333, 84.6667)
  line L2 (613.8333, 42.3333) -> (613.8333, 84.6667)
  line L3 (601.1333, 42.3333) -> (613.8333, 42.3333)
  line L4 (601.1333, 84.6667) -> (601.1333, 42.3333)
  line L5 (313.2667, 84.6667) -> (300.5667, 84.6667)
  line L6 (313.2667, 42.3333) -> (313.2667, 84.6667)
  line L7 (300.5667, 42.3333) -> (313.2667, 42.3333)
  line L8 (300.5667, 84.6667) -> (300.5667, 42.3333)
  line L9 (914.4, 42.3333) -> (901.7, 42.3333)
  line L10 (914.4, 84.6667) -> (914.4, 42.3333)
  line L11 (901.7, 84.6667) -> (914.4, 84.6667)
  line L12 (901.7, 139.7) -> (901.7, 84.6667)
  line L13 (12.7, 139.7) -> (901.7, 139.7)
  line L14 (12.7, 84.6667) -> (12.7, 139.7)
  line L15 (0, 84.6667) -> (12.7, 84.6667)
  line L16 (0, 42.3333) -> (0, 84.6667)
  line L17 (12.7, 42.3333) -> (0, 42.3333)
  line L18 (12.7, 0) -> (12.7, 42.3333)
  line L19 (901.7, 0) -> (12.7, 0)
  line L20 (901.7, 42.3333) -> (901.7, 0)
  line L21 (787.4, 0) -> (127, 0)
  line L22 (787.4, 19.05) -> (787.4, 0)
  line L23 (127, 19.05) -> (787.4, 19.05)
  line L24 (127, 0) -> (127, 19.05)
  line L25 (0, 42.3333) -> (12.7, 42.3333)
  line L26 (0, 0) -> (0, 42.3333)
  line L27 (12.7, 0) -> (0, 0)
  line L28 (12.7, 42.3333) -> (12.7, 0)
  line L29 (12.7, 84.6667) -> (0, 84.6667)
  line L30 (12.7, 139.7) -> (12.7, 84.6667)
  line L31 (0, 139.7) -> (12.7, 139.7)
  line L32 (0, 84.6667) -> (0, 139.7)
  line L33 (914.4, 84.6667) -> (901.7, 84.6667)
  line L34 (914.4, 139.7) -> (914.4, 84.6667)
  line L35 (901.7, 139.7) -> (914.4, 139.7)
  line L36 (901.7, 84.6667) -> (901.7, 139.7)
  line L37 (901.7, 42.3333) -> (914.4, 42.3333)
  line L38 (901.7, 0) -> (901.7, 42.3333)
  line L39 (914.4, 0) -> (901.7, 0)
  line L40 (914.4, 42.3333) -> (914.4, 0)
  point P22 (127, 0)
  point P23 (787.4, 0)
  horizontal L21
  vertical L22
  horizontal L23
  vertical L24
  coincident L19 P22
  dimension "d104" distance P22 P23 = 660.4
  dimension "d105" distance L24 L26 = 127
  dimension "d106" distance L21 L23 = 19.05
extrude "Extrude20" cut sketch "Sketch18" profile of L19 L21 L22 L23 L24 to an object
extrude "Extrude21" cut sketch "Sketch17" profile of L9 L25 L26 L27 L28 to an object
fillet "Fillet2" radius 406.4
fillet "Fillet3" radius 36.83
extrude "Extrude22" cut of existing geometry blind -12.7
extrude "Extrude23" cut sketch "Sketch13" profile of C1 C2 L7 L8 L9 L10 L11 L12 L13 L14 L15 L16 L17 L18 L19 L20 L21 L22 L23 L24 L25 L26 L27 L28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 along normal blind 3.175
sketch "vert outer frame" plane through (1828.8, 0, 0) normal (1, 0, 0) x axis (0, 1, 0)
  line L1 (664.4328, 19.05) -> (249.9672, 19.05)
  line L2 (901.7, 0) -> (787.4, 0)
  line L3 (901.7, 42.3333) -> (901.7, 0)
  line L4 (914.4, 42.3333) -> (901.7, 42.3333)
  line L5 (914.4, 84.6667) -> (914.4, 42.3333)
  line L6 (901.7, 84.6667) -> (914.4, 84.6667)
  line L7 (901.7, 139.7) -> (901.7, 84.6667)
  line L8 (12.7, 139.7) -> (901.7, 139.7)
  line L9 (12.7, 84.6667) -> (12.7, 139.7)
  line L10 (0, 84.6667) -> (12.7, 84.6667)
  line L11 (0, 42.3333) -> (0, 84.6667)
  line L12 (12.7, 42.3333) -> (0, 42.3333)
  line L13 (12.7, 0) -> (12.7, 42.3333)
  line L14 (127, 0) -> (12.7, 0)
  line L15 (313.2667, 84.6667) -> (300.5667, 84.6667)
  line L16 (313.2667, 42.3333) -> (313.2667, 84.6667)
  line L17 (300.5667, 42.3333) -> (313.2667, 42.3333)
  line L18 (300.5667, 84.6667) -> (300.5667, 42.3333)
  line L19 (613.8333, 84.6667) -> (601.1333, 84.6667)
  line L20 (613.8333, 42.3333) -> (613.8333, 84.6667)
  line L21 (601.1333, 42.3333) -> (613.8333, 42.3333)
  line L22 (601.1333, 84.6667) -> (601.1333, 42.3333)
  arc A1 centre (249.9672, -387.35) radius 406.4 clockwise from (127, 0) to (249.9672, 19.05)
  arc A2 centre (664.4328, -387.35) radius 406.4 clockwise from (664.4328, 19.05) to (787.4, 0)
sketch "vert inner frame" plane through (1816.1, 0, 0) normal (1, 0, 0) x axis (0, 1, 0)
  line L1 (889, 0) -> (787.4, 0)
  line L2 (889, 42.3333) -> (889, 0)
  line L3 (914.4, 42.3333) -> (889, 42.3333)
  line L4 (914.4, 84.6667) -> (914.4, 42.3333)
  line L5 (889, 84.6667) -> (914.4, 84.6667)
  line L6 (889, 101.6) -> (889, 84.6667)
  line L7 (25.4, 101.6) -> (889, 101.6)
  line L8 (25.4, 84.6667) -> (25.4, 101.6)
  line L9 (0, 84.6667) -> (25.4, 84.6667)
  line L10 (0, 42.3333) -> (0, 84.6667)
  line L11 (25.4, 42.3333) -> (0, 42.3333)
  line L12 (25.4, 0) -> (25.4, 42.3333)
  line L13 (127, 0) -> (25.4, 0)
  line L14 (664.4328, 19.05) -> (249.9672, 19.05)
  line L15 (313.2667, 84.6667) -> (300.5667, 84.6667)
  line L16 (313.2667, 42.3333) -> (313.2667, 84.6667)
  line L17 (300.5667, 42.3333) -> (313.2667, 42.3333)
  line L18 (300.5667, 84.6667) -> (300.5667, 42.3333)
  line L19 (613.8333, 84.6667) -> (601.1333, 84.6667)
  line L20 (613.8333, 42.3333) -> (613.8333, 84.6667)
  line L21 (601.1333, 42.3333) -> (613.8333, 42.3333)
  line L22 (601.1333, 84.6667) -> (601.1333, 42.3333)
  arc A1 centre (249.9672, -387.35) radius 406.4 clockwise from (127, 0) to (249.9672, 19.05)
  arc A2 centre (664.4328, -387.35) radius 406.4 clockwise from (664.4328, 19.05) to (787.4, 0)
sketch "horiz outer frame" plane through (0, 914.4, 0) normal (0, 1, 0) x axis (-1, 0, 0)
  line L1 (-920.75, 42.3333) -> (-908.05, 42.3333)
  line L2 (-920.75, 84.6667) -> (-920.75, 42.3333)
  line L3 (-908.05, 84.6667) -> (-920.75, 84.6667)
  line L4 (-908.05, 42.3333) -> (-908.05, 84.6667)
  line L5 (-466.725, 42.3333) -> (-454.025, 42.3333)
  line L6 (-466.725, 84.6667) -> (-466.725, 42.3333)
  line L7 (-454.025, 84.6667) -> (-466.725, 84.6667)
  line L8 (-454.025, 42.3333) -> (-454.025, 84.6667)
  line L9 (-249.9672, 19.05) -> (-1578.8328, 19.05)
  line L10 (0, 0) -> (-127, 0)
  line L11 (0, 42.3333) -> (0, 0)
  line L12 (-25.4, 42.3333) -> (0, 42.3333)
  line L13 (-25.4, 84.6667) -> (-25.4, 42.3333)
  line L14 (0, 84.6667) -> (-25.4, 84.6667)
  line L15 (0, 139.7) -> (0, 84.6667)
  line L16 (-1828.8, 139.7) -> (0, 139.7)
  line L17 (-1828.8, 84.6667) -> (-1828.8, 139.7)
  line L18 (-1803.4, 84.6667) -> (-1828.8, 84.6667)
  line L19 (-1803.4, 42.3333) -> (-1803.4, 84.6667)
  line L20 (-1828.8, 42.3333) -> (-1803.4, 42.3333)
  line L21 (-1828.8, 0) -> (-1828.8, 42.3333)
  line L22 (-1701.8, 0) -> (-1828.8, 0)
  line L23 (-1374.775, 42.3333) -> (-1362.075, 42.3333)
  line L24 (-1374.775, 84.6667) -> (-1374.775, 42.3333)
  line L25 (-1362.075, 84.6667) -> (-1374.775, 84.6667)
  line L26 (-1362.075, 42.3333) -> (-1362.075, 84.6667)
  arc A1 centre (-249.9672, -387.35) radius 406.4 clockwise from (-249.9672, 19.05) to (-127, 0)
  arc A2 centre (-1578.8328, -387.35) radius 406.4 clockwise from (-1701.8, 0) to (-1578.8328, 19.05)
sketch "horiz inner frame" plane through (0, 901.7, 0) normal (0, 1, 0) x axis (-1, 0, 0)
  line L1 (-1374.775, 42.3333) -> (-1362.075, 42.3333)
  line L2 (-1374.775, 84.6667) -> (-1374.775, 42.3333)
  line L3 (-1362.075, 84.6667) -> (-1374.775, 84.6667)
  line L4 (-1362.075, 42.3333) -> (-1362.075, 84.6667)
  line L5 (-920.75, 42.3333) -> (-908.05, 42.3333)
  line L6 (-920.75, 84.6667) -> (-920.75, 42.3333)
  line L7 (-908.05, 84.6667) -> (-920.75, 84.6667)
  line L8 (-908.05, 42.3333) -> (-908.05, 84.6667)
  line L9 (-466.725, 42.3333) -> (-454.025, 42.3333)
  line L10 (-466.725, 84.6667) -> (-466.725, 42.3333)
  line L11 (-454.025, 84.6667) -> (-466.725, 84.6667)
  line L12 (-454.025, 42.3333) -> (-454.025, 84.6667)
  line L13 (-249.9672, 19.05) -> (-1578.8328, 19.05)
  line L14 (-12.7, 0) -> (-127, 0)
  line L15 (-12.7, 42.3333) -> (-12.7, 0)
  line L16 (-25.4, 42.3333) -> (-12.7, 42.3333)
  line L17 (-25.4, 84.6667) -> (-25.4, 42.3333)
  line L18 (-12.7, 84.6667) -> (-25.4, 84.6667)
  line L19 (-12.7, 101.6) -> (-12.7, 84.6667)
  line L20 (-1816.1, 101.6) -> (-12.7, 101.6)
  line L21 (-1816.1, 84.6667) -> (-1816.1, 101.6)
  line L22 (-1803.4, 84.6667) -> (-1816.1, 84.6667)
  line L23 (-1803.4, 42.3333) -> (-1803.4, 84.6667)
  line L24 (-1816.1, 42.3333) -> (-1803.4, 42.3333)
  line L25 (-1816.1, 0) -> (-1816.1, 42.3333)
  line L26 (-1701.8, 0) -> (-1816.1, 0)
  arc A1 centre (-1578.8328, -387.35) radius 406.4 clockwise from (-1701.8, 0) to (-1578.8328, 19.05)
  arc A2 centre (-249.9672, -387.35) radius 406.4 clockwise from (-249.9672, 19.05) to (-127, 0)
sketch "vert x3" plane through (454.025, 0, 0) normal (-1, 0, 0) x axis (0, -1, 0)
  line L1 (-25.4, 19.05) -> (-889, 19.05)
  line L2 (-25.4, 42.3333) -> (-25.4, 19.05)
  line L3 (0, 42.3333) -> (-25.4, 42.3333)
  line L4 (0, 84.6667) -> (0, 42.3333)
  line L5 (-25.4, 84.6667) -> (0, 84.6667)
  line L6 (-25.4, 101.6) -> (-25.4, 84.6667)
  line L7 (-300.5667, 101.6) -> (-25.4, 101.6)
  line L8 (-300.5667, 63.5) -> (-300.5667, 101.6)
  line L9 (-313.2667, 63.5) -> (-300.5667, 63.5)
  line L10 (-313.2667, 101.6) -> (-313.2667, 63.5)
  line L11 (-601.1333, 101.6) -> (-313.2667, 101.6)
  line L12 (-601.1333, 63.5) -> (-601.1333, 101.6)
  line L13 (-613.8333, 63.5) -> (-601.1333, 63.5)
  line L14 (-613.8333, 101.6) -> (-613.8333, 63.5)
  line L15 (-889, 101.6) -> (-613.8333, 101.6)
  line L16 (-889, 84.6667) -> (-889, 101.6)
  line L17 (-914.4, 84.6667) -> (-889, 84.6667)
  line L18 (-914.4, 42.3333) -> (-914.4, 84.6667)
  line L19 (-889, 42.3333) -> (-914.4, 42.3333)
  line L20 (-889, 19.05) -> (-889, 42.3333)
sketch "horiz x2" plane through (0, 613.8333, 0) normal (0, 1, 0) x axis (-1, 0, 0)
  line L1 (-1803.4, 101.6) -> (-25.4, 101.6)
  line L2 (-1803.4, 84.6667) -> (-1803.4, 101.6)
  line L3 (-1828.8, 84.6667) -> (-1803.4, 84.6667)
  line L4 (-1828.8, 42.3333) -> (-1828.8, 84.6667)
  line L5 (-1803.4, 42.3333) -> (-1828.8, 42.3333)
  line L6 (-1803.4, 19.05) -> (-1803.4, 42.3333)
  line L7 (-1374.775, 19.05) -> (-1803.4, 19.05)
  line L8 (-1374.775, 63.5) -> (-1374.775, 19.05)
  line L9 (-1362.075, 63.5) -> (-1374.775, 63.5)
  line L10 (-1362.075, 19.05) -> (-1362.075, 63.5)
  line L11 (-920.75, 19.05) -> (-1362.075, 19.05)
  line L12 (-920.75, 63.5) -> (-920.75, 19.05)
  line L13 (-908.05, 63.5) -> (-920.75, 63.5)
  line L14 (-908.05, 19.05) -> (-908.05, 63.5)
  line L15 (-466.725, 19.05) -> (-908.05, 19.05)
  line L16 (-466.725, 63.5) -> (-466.725, 19.05)
  line L17 (-454.025, 63.5) -> (-466.725, 63.5)
  line L18 (-454.025, 19.05) -> (-454.025, 63.5)
  line L19 (-25.4, 19.05) -> (-454.025, 19.05)
  line L20 (-25.4, 42.3333) -> (-25.4, 19.05)
  line L21 (0, 42.3333) -> (-25.4, 42.3333)
  line L22 (0, 84.6667) -> (0, 42.3333)
  line L23 (-25.4, 84.6667) -> (0, 84.6667)
  line L24 (-25.4, 101.6) -> (-25.4, 84.6667)
sketch "horiz outer frame w_cutout" plane through (0, 0, 0) normal (0, -1, 0) x axis (1, 0, 0)
  line L1 (1828.8, 0) -> (1701.8, 0)
  line L2 (1828.8, 42.3333) -> (1828.8, 0)
  line L3 (1803.4, 42.3333) -> (1828.8, 42.3333)
  line L4 (1803.4, 84.6667) -> (1803.4, 42.3333)
  line L5 (1828.8, 84.6667) -> (1803.4, 84.6667)
  line L6 (1828.8, 139.7) -> (1828.8, 84.6667)
  line L7 (0, 139.7) -> (1828.8, 139.7)
  line L8 (0, 84.6667) -> (0, 139.7)
  line L9 (25.4, 84.6667) -> (0, 84.6667)
  line L10 (25.4, 42.3333) -> (25.4, 84.6667)
  line L11 (0, 42.3333) -> (25.4, 42.3333)
  line L12 (0, 0) -> (0, 42.3333)
  line L13 (127, 0) -> (0, 0)
  line L14 (984.25, 19.05) -> (249.9672, 19.05)
  line L15 (984.25, 33.02) -> (984.25, 19.05)
  line L16 (1099.82, 69.85) -> (1021.08, 69.85)
  line L17 (1136.65, 19.05) -> (1136.65, 33.02)
  line L18 (1578.8328, 19.05) -> (1136.65, 19.05)
  line L19 (1374.775, 84.6667) -> (1362.075, 84.6667)
  line L20 (1374.775, 42.3333) -> (1374.775, 84.6667)
  line L21 (1362.075, 42.3333) -> (1374.775, 42.3333)
  line L22 (1362.075, 84.6667) -> (1362.075, 42.3333)
  line L23 (466.725, 84.6667) -> (454.025, 84.6667)
  line L24 (466.725, 42.3333) -> (466.725, 84.6667)
  line L25 (454.025, 42.3333) -> (466.725, 42.3333)
  line L26 (454.025, 84.6667) -> (454.025, 42.3333)
  line L27 (920.75, 84.6667) -> (908.05, 84.6667)
  line L28 (920.75, 42.3333) -> (920.75, 84.6667)
  line L29 (908.05, 42.3333) -> (920.75, 42.3333)
  line L30 (908.05, 84.6667) -> (908.05, 42.3333)
  arc A1 centre (249.9672, -387.35) radius 406.4 clockwise from (127, 0) to (249.9672, 19.05)
  arc A2 centre (1021.08, 33.02) radius 36.83 clockwise from (984.25, 33.02) to (1021.08, 69.85)
  arc A3 centre (1099.82, 33.02) radius 36.83 clockwise from (1099.82, 69.85) to (1136.65, 33.02)
  arc A4 centre (1578.8328, -387.35) radius 406.4 clockwise from (1578.8328, 19.05) to (1701.8, 0)
sketch "horiz inner frame w_cutout" plane through (0, 12.7, 0) normal (0, -1, 0) x axis (1, 0, 0)
  line L1 (1816.1, 0) -> (1701.8, 0)
  line L2 (1816.1, 42.3333) -> (1816.1, 0)
  line L3 (1803.4, 42.3333) -> (1816.1, 42.3333)
  line L4 (1803.4, 84.6667) -> (1803.4, 42.3333)
  line L5 (1816.1, 84.6667) -> (1803.4, 84.6667)
  line L6 (1816.1, 101.6) -> (1816.1, 84.6667)
  line L7 (12.7, 101.6) -> (1816.1, 101.6)
  line L8 (12.7, 84.6667) -> (12.7, 101.6)
  line L9 (25.4, 84.6667) -> (12.7, 84.6667)
  line L10 (25.4, 42.3333) -> (25.4, 84.6667)
  line L11 (12.7, 42.3333) -> (25.4, 42.3333)
  line L12 (12.7, 0) -> (12.7, 42.3333)
  line L13 (127, 0) -> (12.7, 0)
  line L14 (984.25, 19.05) -> (249.9672, 19.05)
  line L15 (984.25, 33.02) -> (984.25, 19.05)
  line L16 (1099.82, 69.85) -> (1021.08, 69.85)
  line L17 (1136.65, 19.05) -> (1136.65, 33.02)
  line L18 (1578.8328, 19.05) -> (1136.65, 19.05)
  line L19 (466.725, 84.6667) -> (454.025, 84.6667)
  line L20 (466.725, 42.3333) -> (466.725, 84.6667)
  line L21 (454.025, 42.3333) -> (466.725, 42.3333)
  line L22 (454.025, 84.6667) -> (454.025, 42.3333)
  line L23 (920.75, 84.6667) -> (908.05, 84.6667)
  line L24 (920.75, 42.3333) -> (920.75, 84.6667)
  line L25 (908.05, 42.3333) -> (920.75, 42.3333)
  line L26 (908.05, 84.6667) -> (908.05, 42.3333)
  line L27 (1374.775, 84.6667) -> (1362.075, 84.6667)
  line L28 (1374.775, 42.3333) -> (1374.775, 84.6667)
  line L29 (1362.075, 42.3333) -> (1374.775, 42.3333)
  line L30 (1362.075, 84.6667) -> (1362.075, 42.3333)
  arc A1 centre (249.9672, -387.35) radius 406.4 clockwise from (127, 0) to (249.9672, 19.05)
  arc A2 centre (1021.08, 33.02) radius 36.83 clockwise from (984.25, 33.02) to (1021.08, 69.85)
  arc A3 centre (1099.82, 33.02) radius 36.83 clockwise from (1099.82, 69.85) to (1136.65, 33.02)
  arc A4 centre (1578.8328, -387.35) radius 406.4 clockwise from (1578.8328, 19.05) to (1701.8, 0)
named bodies: "left vert1", "front horizontal", "vert2", "vert3", "vert4", "right vert5", "horizontal (1)", "horizontal (2)", "rear horiz", "front horiz sup", "rear horiz sup", "right vert sup", "left vert sup", "base", "flex", "faceplate"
